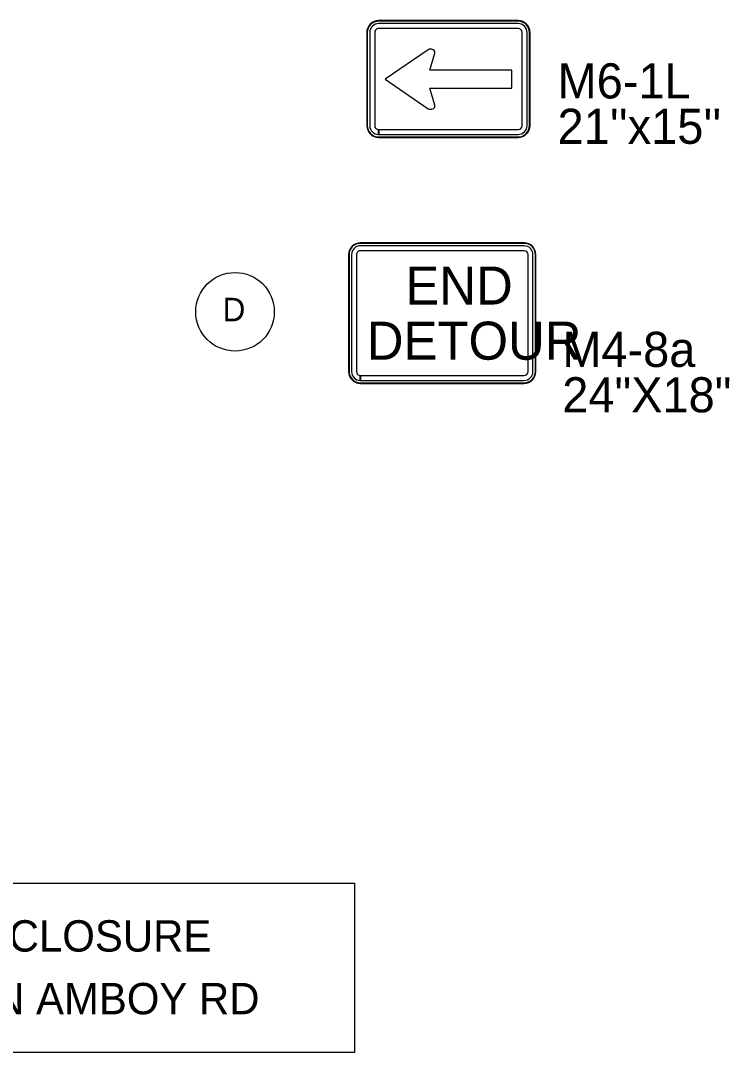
# Model space of a CAD drawing. Extents: x 886234 to 968767, y 455416 to 684046.
# Drawn here: x 935407 to 938800, y 525352 to 530289 of the extents above; entities that cross this region are included whole.
import ezdxf

# ---------------------------------------------------------------- set-up
doc = ezdxf.new("R2010")
doc.units = 0
for name, color, linetype in [('TC DEV SIGN BLACK 239', 7, 'Continuous'), ('TC DEV SIGN BLACK ZERO', 7, 'Continuous'), ('TC DEV SIGN ORANGE', 7, 'Continuous'), ('TC DEV SIGN WHITE', 7, 'Continuous'), ('TC LABEL TEXT', 7, 'Continuous')]:
    doc.layers.add(name, color=color, linetype=linetype)

msp = doc.modelspace()

# ---------------------------------------------------------------- linework, layer by layer
at = {"layer": 'TC DEV SIGN BLACK 239'}
for p, q in [((937788.7, 530274.6), (937120.8, 530274.6)), ((937078.2, 530232), (937078.2, 529786.8)), ((937101.9, 530232), (937101.9, 529786.8)), ((937788.7, 530251), (937120.8, 530251)), ((937807.6, 529786.8), (937807.6, 530232)), ((937831.3, 529786.8), (937831.3, 530232)), ((937357.2, 530149.9), (937151.9, 530008.5)), ((937366.1, 530052.1), (937389.3, 530132.7)), ((937758, 530052.1), (937366.1, 530052.1)), ((937758, 529966.3), (937758, 530052.1)), ((937151.9, 530008.5), (937357.2, 529867.1)), ((937389.3, 529884.3), (937366.2, 529966.3)), ((937366.2, 529966.3), (937758, 529966.3)), ((937120.8, 529744.2), (937120.8, 529767.8)), ((937121, 529767.8), (937788.7, 529767.8)), ((937121, 529767.8), (937121, 529744.2)), ((937121, 529744.2), (937788.7, 529744.2))]:
    msp.add_line(p, q, dxfattribs=at)
for centre, major_axis, ratio, start_param, end_param in [((937120.8, 530232), (42.6, 0), 0.999865, 1.570796, 3.141593), ((937788.7, 530232), (42.6, 0), 0.999865, 0, 1.570796), ((937120.8, 530232), (18.9, 0), 0.999865, 1.570796, 3.141593), ((937788.7, 530232), (18.9, 0), 0.999865, 0, 1.570796), ((937369.2, 530137.3), (-21.1, 0), 0.720018, 2.830616, 5.313575), ((937369.2, 529879.6), (-21.1, 0), 0.720018, 0.969609, 3.452568), ((937120.8, 529786.8), (42.6, 0), 0.999865, 3.141593, 4.712389), ((937120.8, 529786.8), (18.9, 0), 0.999865, 3.141593, 4.712389), ((937788.7, 529786.8), (42.6, 0), 0.999865, 4.712389, 6.283185), ((937788.7, 529786.8), (18.9, 0), 0.999865, 4.712389, 6.283185)]:
    msp.add_ellipse(centre, major_axis=major_axis, ratio=ratio, start_param=start_param, end_param=end_param, dxfattribs=at)
at = {"layer": 'TC DEV SIGN BLACK ZERO'}
for p, q in [((937788.7, 530288.8), (937120.8, 530288.8)), ((937120.8, 530286.5), (937120.8, 530286.5)), ((937788.7, 530286.5), (937120.8, 530286.5)), ((937788.7, 530286.5), (937788.7, 530286.5)), ((937064, 530232), (937064, 529786.8)), ((937066.4, 530232), (937066.4, 529786.8)), ((937066.4, 530232), (937066.4, 530232)), ((937843.1, 530232), (937843.1, 530232)), ((937843.1, 529786.8), (937843.1, 530232)), ((937845.5, 529786.8), (937845.5, 530232)), ((937066.4, 529786.8), (937066.4, 529786.8)), ((937843.1, 529786.8), (937843.1, 529786.8)), ((937120.8, 529730), (937120.8, 529732.4)), ((937120.8, 529732.4), (937120.8, 529732.3)), ((937120.8, 529732.4), (937788.7, 529732.4)), ((937120.8, 529732.4), (937120.8, 529730)), ((937120.8, 529730), (937788.7, 529730)), ((937788.7, 529732.3), (937788.7, 529732.4)), ((937817.3, 529225.3), (937033.2, 529225.3)), ((937033.2, 529223), (937033.2, 529223)), ((937817.3, 529223), (937033.2, 529223)), ((937817.3, 529211.3), (937033.2, 529211.3)), ((937817.3, 529188), (937033.2, 529188)), ((937817.3, 529223), (937817.3, 529223)), ((936977.2, 529169.3), (936977.1, 528609.3)), ((936979.5, 529169.3), (936979.4, 528609.3)), ((936979.5, 529169.3), (936979.5, 529169.3)), ((936991.2, 529169.3), (936991.1, 528609.3)), ((937014.5, 529169.3), (937014.5, 528609.3)), ((937835.9, 528609.3), (937836, 529169.3)), ((937859.2, 528609.3), (937859.3, 529169.3)), ((937870.9, 528609.3), (937871, 529169.3)), ((937871, 529169.3), (937871, 529169.3)), ((937873.3, 528609.3), (937873.3, 529169.3)), ((936979.5, 528609.3), (936979.4, 528609.3)), ((937033.1, 528567.3), (937033.1, 528590.7)), ((937033.4, 528590.7), (937817.2, 528590.7)), ((937033.4, 528590.7), (937033.4, 528567.3)), ((937870.9, 528609.3), (937870.9, 528609.3)), ((937033.1, 528553.3), (937033.1, 528555.7)), ((937033.1, 528555.7), (937033.1, 528555.7)), ((937033.2, 528555.7), (937817.2, 528555.7)), ((937033.2, 528555.7), (937033.2, 528553.3)), ((937033.2, 528553.3), (937817.2, 528553.3)), ((937033.4, 528567.3), (937817.2, 528567.3)), ((937817.2, 528555.7), (937817.2, 528555.7))]:
    msp.add_line(p, q, dxfattribs=at)
for centre, major_axis, start_param, end_param in [((937120.8, 530232), (56.8, 0), 1.570796, 3.141593), ((937120.8, 530232), (54.4, 0), 1.570796, 3.141593), ((937788.7, 530232), (56.8, 0), 0, 1.570796), ((937788.7, 530232), (54.4, 0), 0, 1.570796), ((937120.8, 529786.8), (56.8, 0), 3.141593, 4.712389), ((937120.8, 529786.8), (54.4, 0), 3.141593, 4.712389), ((937788.7, 529786.8), (56.8, 0), 4.712389, 6.283185), ((937788.7, 529786.8), (54.4, 0), 4.712389, 6.283185), ((937033.2, 529169.3), (56, 0), 1.570796, 3.141593), ((937033.2, 529169.3), (53.7, 0), 1.570796, 3.141593), ((937033.2, 529169.3), (42, 0), 1.570796, 3.141593), ((937033.2, 529169.3), (18.7, 0), 1.570796, 3.141593), ((937817.3, 529169.3), (56, 0), 0, 1.570796), ((937817.3, 529169.3), (53.7, 0), 0, 1.570796), ((937817.3, 529169.3), (42, 0), 0, 1.570796), ((937817.3, 529169.3), (18.7, 0), 0, 1.570796), ((937033.1, 528609.3), (56, 0), 3.141593, 4.712389), ((937033.1, 528609.3), (53.7, 0), 3.141593, 4.712389), ((937033.1, 528609.3), (42, 0), 3.141593, 4.712389), ((937033.1, 528609.3), (18.7, 0), 3.141593, 4.712389), ((937817.2, 528609.3), (42, 0), 4.712389, 6.283185), ((937817.2, 528609.3), (18.7, 0), 4.712389, 6.283185), ((937817.2, 528609.3), (56, 0), 4.712389, 6.283185), ((937817.2, 528609.3), (53.7, 0), 4.712389, 6.283185)]:
    msp.add_ellipse(centre, major_axis=major_axis, ratio=0.999865, start_param=start_param, end_param=end_param, dxfattribs=at)
at = {"layer": 'TC DEV SIGN ORANGE'}
for p, q in [((937817.3, 529225.3), (937033.2, 529225.3)), ((936977.2, 529169.3), (936977.1, 528609.3)), ((937873.3, 528609.3), (937873.3, 529169.3)), ((937033.1, 528553.3), (937817.2, 528553.3))]:
    msp.add_line(p, q, dxfattribs=at)
for centre, start_param, end_param in [((937033.2, 529169.3), 1.570796, 3.141593), ((937817.3, 529169.3), 0, 1.570796), ((937033.1, 528609.3), 3.141593, 4.712389), ((937817.2, 528609.3), 4.712389, 6.283185)]:
    msp.add_ellipse(centre, major_axis=(56, 0), ratio=0.999865, start_param=start_param, end_param=end_param, dxfattribs=at)
at = {"layer": 'TC DEV SIGN WHITE'}
for p, q in [((937788.7, 530288.8), (937120.8, 530288.8)), ((937064, 530232), (937064, 529786.8)), ((937845.5, 529786.8), (937845.5, 530232)), ((937120.8, 529730), (937788.7, 529730))]:
    msp.add_line(p, q, dxfattribs=at)
for centre, start_param, end_param in [((937120.8, 530232), 1.570796, 3.141593), ((937788.7, 530232), 0, 1.570796), ((937120.8, 529786.8), 3.141593, 4.712389), ((937788.7, 529786.8), 4.712389, 6.283185)]:
    msp.add_ellipse(centre, major_axis=(56.8, 0), ratio=0.999865, start_param=start_param, end_param=end_param, dxfattribs=at)
at = {"layer": 'TC LABEL TEXT'}
msp.add_lwpolyline([(931806, 526162), (937004.8, 526162), (937004.8, 525352), (931806, 525352)], close=True, dxfattribs=at)
msp.add_circle((936433.4, 528895.7), 188.1, dxfattribs=at)

# ---------------------------------------------------------------- texts
at = {"layer": 'TC DEV SIGN BLACK ZERO'}
for s, height, p in [('M6-1L', 168, (937977.3, 529916.6)), ("21''x15''", 168, (937977.3, 529699.3)), ('END', 182, (937248.8, 528930.3)), ('DETOUR', 182, (937064.2, 528666.4)), ('M4-8a', 168, (938000, 528631.8)), ('24"X18"', 168, (938000, 528414.5))]:
    msp.add_text(s, height=height, rotation=360, dxfattribs=at).set_placement(p)
at = {"layer": 'TC LABEL TEXT'}
for s, height, p in [('D', 112.5, (936374.2, 528850.2)), ('SEE RSD 1101.03, SHEET 2 FOR CLOSURE ', 150, (932206.5, 525834.2)), ('SIGN AND DEVICE PLACEMENT ON AMBOY RD', 150, (932014.6, 525534.2))]:
    msp.add_text(s, height=height, dxfattribs=at).set_placement(p)

doc.saveas('drawing.dxf')
